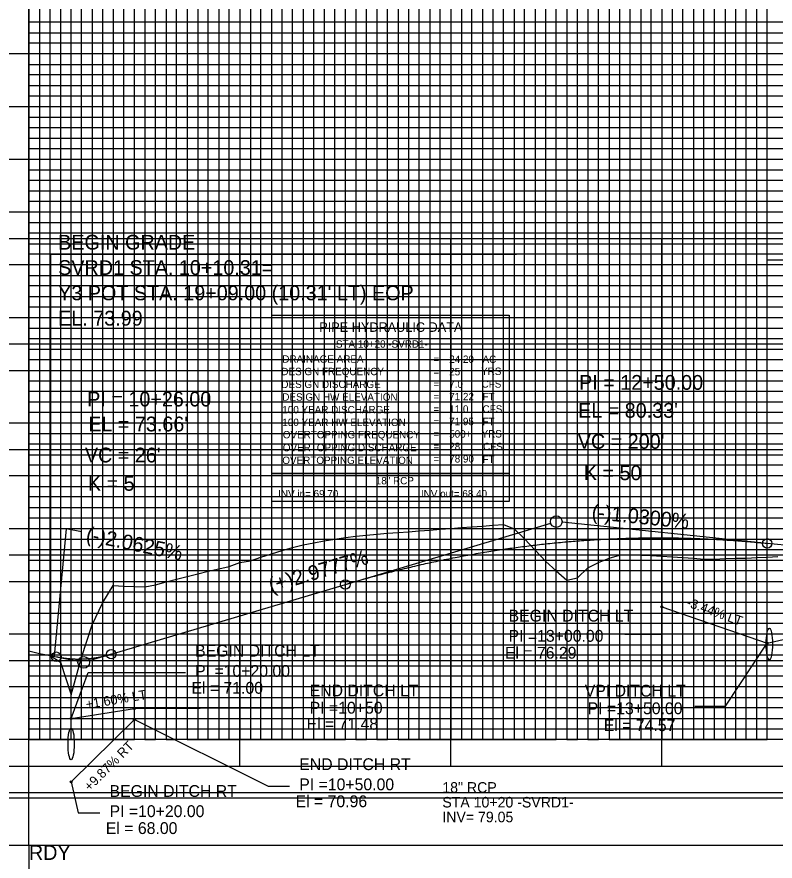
# Model space of a CAD drawing. Extents: x 2345490 to 2436403, y 465165 to 573888.
# Drawn here: x 2381761.1 to 2382120.5, y 510396.8 to 510796.9 of the extents above; entities that cross this region are included whole.
import ezdxf

# ---------------------------------------------------------------- set-up
doc = ezdxf.new("R2010")
doc.units = 0
for name, color, linetype in [('Old_Level_1', 7, 'Continuous'), ('Old_Level_18', 7, 'Continuous'), ('Old_Level_2', 7, 'Continuous'), ('Old_Level_3', 7, 'Continuous'), ('Old_Level_4', 7, 'Continuous'), ('Old_Level_41', 7, 'Continuous'), ('Old_Level_42', 7, 'Continuous'), ('Old_Level_43', 7, 'Continuous'), ('Old_Level_50', 7, 'Continuous'), ('Old_Level_51', 7, 'Continuous'), ('Old_Level_57', 7, 'Continuous'), ('Old_Level_63', 7, 'Continuous'), ('Prop Vertical Profile Grade', 7, 'Continuous')]:
    doc.layers.add(name, color=color, linetype=linetype)

msp = doc.modelspace()

# ---------------------------------------------------------------- linework, layer by layer
at = {"layer": 'Old_Level_1'}
msp.add_lwpolyline([(2381766.799, 510496.38628), (2381771.799, 510495.26652), (2381776.799, 510494.29703), (2381781.799, 510491.09236), (2381786.799, 510475.545), (2381791.799, 510493.23682), (2381796.799, 510508.82896), (2381801.799, 510519.43585), (2381806.799, 510527.46772), (2381811.799, 510527.16316), (2381816.799, 510526.92701), (2381821.799, 510526.73293), (2381826.799, 510527.68325), (2381831.799, 510529.13877), (2381836.799, 510530.47008), (2381841.799, 510531.75771), (2381846.799, 510533.00023), (2381851.799, 510534.19626), (2381856.799, 510535.34447), (2381861.799, 510536.44358), (2381866.799, 510538.26535), (2381871.799, 510539.18964), (2381876.799, 510540.85295), (2381881.799, 510542.44657), (2381886.799, 510543.96872), (2381891.799, 510545.41772), (2381896.799, 510546.68661), (2381901.799, 510547.6733), (2381906.799, 510548.57556), (2381911.799, 510549.39239), (2381916.799, 510550.12286), (2381921.799, 510550.76618), (2381926.799, 510551.32163), (2381931.799, 510551.78859), (2381936.799, 510552.17014), (2381941.799, 510552.5288), (2381946.799, 510552.88746), (2381951.799, 510553.34688), (2381956.799, 510553.71799), (2381961.799, 510554.0891), (2381966.799, 510554.46021), (2381971.799, 510554.83132), (2381976.799, 510555.20243), (2381981.799, 510555.57354), (2381986.799, 510555.94465), (2381991.799, 510556.34881), (2381996.799, 510554.23512), (2382001.799, 510549.54421), (2382006.799, 510544.21219), (2382011.799, 510538.85622), (2382016.799, 510534.42474), (2382021.799, 510529.99327), (2382026.799, 510531.06065), (2382031.799, 510535.83309), (2382036.799, 510538.39836), (2382041.799, 510540.30035), (2382046.799, 510541.74515), (2382051.799, 510541.98873), (2382056.799, 510541.81563), (2382061.799, 510541.64254), (2382066.799, 510541.39711), (2382071.799, 510541.05134), (2382076.799, 510540.72909), (2382081.799, 510540.40571), (2382086.799, 510539.94628), (2382091.799, 510539.9297), (2382096.799, 510540.14654), (2382101.799, 510540.31913), (2382106.799, 510540.43366), (2382111.799, 510540.67643), (2382116.799, 510540.9192), (2382121.799, 510541.16197)], dxfattribs=at)
at = {"layer": 'Old_Level_18'}
msp.add_lwpolyline([(2383216.79875, 511479.3835), (2381716.79875, 511479.3835), (2381716.79875, 510429.3835), (2383216.79875, 510429.3835)], close=True, dxfattribs=at)
at = {"layer": 'Old_Level_2'}
for p, q in [((2381777.109, 510684.44001), (2381997.96282, 510684.47515)), ((2381777.109, 510494.2375), (2381777.109, 510684.44001)), ((2382116.799, 510681.70631), (2382256.61089, 510681.70631)), ((2382116.799, 510547.3835), (2382116.799, 510681.70631)), ((2382116.799, 510547.3835), (2382019.53453, 510557.40174)), ((2381784.50848, 510554.29431), (2381778.8217, 510494.02737)), ((2381791.76888, 510552.84223), (2381784.50848, 510554.29431)), ((2381916.799, 510527.90671), (2382014.16336, 510556.89869)), ((2381779.799, 510493.66475), (2381790.10569, 510491.539)), ((2381805.799, 510494.85448), (2381795.43464, 510491.76831))]:
    msp.add_line(p, q, dxfattribs=at)
for centre, radius in [((2382016.799, 510557.6835), 2.75), ((2382116.799, 510547.3835), 2.25), ((2381916.799, 510527.90671), 2.25), ((2381805.799, 510494.85448), 2.25), ((2381779.799, 510493.66475), 2.25), ((2381792.799, 510490.9835), 2.75)]:
    msp.add_circle(centre, radius, dxfattribs=at)
at = {"layer": 'Old_Level_3'}
for p, q in [((2382066.799, 510504.39502), (2382066.799, 510517.2835)), ((2382066.799, 510517.2835), (2382116.799, 510500.0835)), ((2382116.799, 510500.0835), (2382166.799, 510511.3835)), ((2382049.36634, 510504.39502), (2382066.799, 510504.39502)), ((2382097.05969, 510470.20539), (2382116.799, 510500.0835)), ((2381786.799, 510464.3835), (2381794.9392, 510486.13954)), ((2381794.9392, 510486.13954), (2381841.03359, 510486.13954)), ((2381786.799, 510464.3835), (2381816.799, 510469.1835)), ((2381816.799, 510469.1835), (2381879.16663, 510469.46159)), ((2381879.16663, 510469.46159), (2381892.35737, 510469.46159)), ((2382082.54842, 510470.20539), (2382097.05969, 510470.20539)), ((2381786.799, 510434.3835), (2381816.799, 510463.9835)), ((2381816.799, 510463.9835), (2381880.13742, 510432.37177)), ((2381786.799, 510434.3835), (2381790.19861, 510419.66303)), ((2381880.13742, 510432.37177), (2381890.40218, 510432.37177)), ((2381790.19861, 510419.66303), (2381800.46337, 510419.66303))]:
    msp.add_line(p, q, dxfattribs=at)
for centre in [(2382066.799, 510517.2835), (2382116.799, 510500.0835), (2381816.799, 510469.1835), (2381786.799, 510464.3835), (2381816.799, 510463.9835), (2381786.799, 510434.3835)]:
    msp.add_circle(centre, 0.5, dxfattribs=at)
for centre in [(2382117.799, 510499.6835), (2381786.799, 510452.3835)]:
    msp.add_ellipse(centre, major_axis=(0, 7.5), ratio=0.195724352, dxfattribs=at)
at = {"layer": 'Old_Level_4'}
for p, q in [((2381882.02849, 510655.45163), (2381994.52849, 510655.45163)), ((2381882.02849, 510580.45163), (2381882.02849, 510655.45163)), ((2381994.52849, 510655.45163), (2381994.52849, 510580.45163)), ((2381994.52849, 510580.45163), (2381882.02849, 510580.45163))]:
    msp.add_line(p, q, dxfattribs=at)
msp.add_lwpolyline([(2381882.02849, 510580.45163), (2381994.52849, 510580.45163), (2381994.52849, 510567.23663), (2381882.02849, 510567.23663)], close=True, dxfattribs=at)
at = {"layer": 'Old_Level_41'}
msp.add_line((2383216.79875, 510454.3835), (2381716.79875, 510454.3835), dxfattribs=at)
for points in [[(2381766.79875, 511479.3835), (2381766.79875, 510454.3835), (2381816.79875, 510454.3835), (2381816.79875, 511479.3835)], [(2381791.79875, 510454.3835), (2381791.79875, 511479.3835)], [(2381841.79875, 511479.3835), (2381841.79875, 510454.3835), (2381891.79875, 510454.3835), (2381891.79875, 511479.3835)], [(2381866.79875, 511479.3835), (2381866.79875, 510454.3835), (2381916.79875, 510454.3835), (2381916.79875, 511479.3835)], [(2381941.79875, 511479.3835), (2381941.79875, 510454.3835), (2381991.79875, 510454.3835), (2381991.79875, 511479.3835)], [(2381966.79875, 511479.3835), (2381966.79875, 510454.3835), (2382016.79875, 510454.3835), (2382016.79875, 511479.3835)], [(2382041.79875, 511479.3835), (2382041.79875, 510454.3835), (2382091.79875, 510454.3835), (2382091.79875, 511479.3835)], [(2382066.79875, 511479.3835), (2382066.79875, 510454.3835), (2382116.79875, 510454.3835), (2382116.79875, 511479.3835)], [(2383216.79875, 510779.3835), (2381716.79875, 510779.3835), (2381716.79875, 510729.3835), (2383216.79875, 510729.3835)], [(2383216.79875, 510704.3835), (2381716.79875, 510704.3835), (2381716.79875, 510754.3835), (2383216.79875, 510754.3835)], [(2383216.79875, 510679.3835), (2381716.79875, 510679.3835), (2381716.79875, 510629.3835), (2383216.79875, 510629.3835)], [(2383216.79875, 510579.3835), (2381716.79875, 510579.3835), (2381716.79875, 510529.3835), (2383216.79875, 510529.3835)], [(2383216.79875, 510504.3835), (2381716.79875, 510504.3835), (2381716.79875, 510554.3835), (2383216.79875, 510554.3835)], [(2383216.79875, 510479.3835), (2381716.79875, 510479.3835)]]:
    msp.add_lwpolyline(points, dxfattribs=at)
at = {"layer": 'Old_Level_42'}
msp.add_lwpolyline([(2383216.79875, 510604.3835), (2381716.79875, 510604.3835), (2381716.79875, 510654.3835), (2383216.79875, 510654.3835)], dxfattribs=at)
at = {"layer": 'Old_Level_43'}
for points in [[(2381771.79875, 511479.3835), (2381771.79875, 510454.3835), (2381776.79875, 510454.3835), (2381776.79875, 511479.3835)], [(2381781.79875, 511479.3835), (2381781.79875, 510454.3835), (2381786.79875, 510454.3835), (2381786.79875, 511479.3835)], [(2381796.79875, 511479.3835), (2381796.79875, 510454.3835), (2381801.79875, 510454.3835), (2381801.79875, 511479.3835)], [(2381806.79875, 511479.3835), (2381806.79875, 510454.3835), (2381811.79875, 510454.3835), (2381811.79875, 511479.3835)], [(2381821.79875, 511479.3835), (2381821.79875, 510454.3835), (2381826.79875, 510454.3835), (2381826.79875, 511479.3835)], [(2381831.79875, 511479.3835), (2381831.79875, 510454.3835), (2381836.79875, 510454.3835), (2381836.79875, 511479.3835)], [(2381846.79875, 511479.3835), (2381846.79875, 510454.3835), (2381851.79875, 510454.3835), (2381851.79875, 511479.3835)], [(2381856.79875, 511479.3835), (2381856.79875, 510454.3835), (2381861.79875, 510454.3835), (2381861.79875, 511479.3835)], [(2381871.79875, 511479.3835), (2381871.79875, 510454.3835), (2381876.79875, 510454.3835), (2381876.79875, 511479.3835)], [(2381881.79875, 511479.3835), (2381881.79875, 510454.3835), (2381886.79875, 510454.3835), (2381886.79875, 511479.3835)], [(2381896.79875, 511479.3835), (2381896.79875, 510454.3835), (2381901.79875, 510454.3835), (2381901.79875, 511479.3835)], [(2381906.79875, 511479.3835), (2381906.79875, 510454.3835), (2381911.79875, 510454.3835), (2381911.79875, 511479.3835)], [(2381921.79875, 511479.3835), (2381921.79875, 510454.3835), (2381926.79875, 510454.3835), (2381926.79875, 511479.3835)], [(2381931.79875, 510454.3835), (2381936.79875, 510454.3835), (2381936.79875, 511479.3835)], [(2381931.79875, 511479.3835), (2381931.79875, 510454.3835)], [(2381946.79875, 511479.3835), (2381946.79875, 510454.3835), (2381951.79875, 510454.3835), (2381951.79875, 511479.3835)], [(2381956.79875, 511479.3835), (2381956.79875, 510454.3835), (2381961.79875, 510454.3835), (2381961.79875, 511479.3835)], [(2381971.79875, 511479.3835), (2381971.79875, 510454.3835), (2381976.79875, 510454.3835), (2381976.79875, 511479.3835)], [(2381981.79875, 511479.3835), (2381981.79875, 510454.3835), (2381986.79875, 510454.3835), (2381986.79875, 511479.3835)], [(2381996.79875, 511479.3835), (2381996.79875, 510454.3835), (2382001.79875, 510454.3835), (2382001.79875, 511479.3835)], [(2382006.79875, 511479.3835), (2382006.79875, 510454.3835), (2382011.79875, 510454.3835), (2382011.79875, 511479.3835)], [(2382021.79875, 511479.3835), (2382021.79875, 510454.3835), (2382026.79875, 510454.3835), (2382026.79875, 511479.3835)], [(2382031.79875, 511479.3835), (2382031.79875, 510454.3835), (2382036.79875, 510454.3835), (2382036.79875, 511479.3835)], [(2382046.79875, 511479.3835), (2382046.79875, 510454.3835), (2382051.79875, 510454.3835), (2382051.79875, 511479.3835)], [(2382056.79875, 511479.3835), (2382056.79875, 510454.3835), (2382061.79875, 510454.3835), (2382061.79875, 511479.3835)], [(2382071.79875, 511479.3835), (2382071.79875, 510454.3835), (2382076.79875, 510454.3835), (2382076.79875, 511479.3835)], [(2382081.79875, 511479.3835), (2382081.79875, 510454.3835), (2382086.79875, 510454.3835), (2382086.79875, 511479.3835)], [(2382096.79875, 511479.3835), (2382096.79875, 510454.3835), (2382111.79875, 510454.3835), (2382111.79875, 511479.3835)], [(2382101.79875, 511479.3835), (2382101.79875, 510454.3835), (2382106.79875, 510454.3835), (2382106.79875, 511479.3835)], [(2382101.79875, 511478.7835), (2382101.79875, 510454.3835), (2382106.79875, 510454.3835), (2382106.79875, 511478.7835)], [(2383166.79875, 510794.3835), (2381766.79875, 510794.3835), (2381766.79875, 510789.3835), (2383166.79875, 510789.3835)], [(2383166.79875, 510784.3835), (2381766.79875, 510784.3835), (2381766.79875, 510774.3835), (2383166.79875, 510774.3835)], [(2383166.79875, 510769.3835), (2381766.79875, 510769.3835), (2381766.79875, 510764.3835), (2383166.79875, 510764.3835)], [(2383166.79875, 510759.3835), (2381766.79875, 510759.3835), (2381766.79875, 510749.3835), (2383166.79875, 510749.3835)], [(2383166.79875, 510744.3835), (2381766.79875, 510744.3835), (2381766.79875, 510739.3835), (2383166.79875, 510739.3835)], [(2383166.79875, 510734.3835), (2381766.79875, 510734.3835), (2381766.79875, 510724.3835), (2383166.79875, 510724.3835)], [(2383166.79875, 510719.3835), (2381766.79875, 510719.3835), (2381766.79875, 510714.3835), (2383166.79875, 510714.3835)], [(2383166.79875, 510709.3835), (2381766.79875, 510709.3835), (2381766.79875, 510699.3835), (2383166.79875, 510699.3835)], [(2383166.79875, 510694.3835), (2381766.79875, 510694.3835), (2381766.79875, 510689.3835), (2383166.79875, 510689.3835)], [(2383166.79875, 510684.3835), (2381766.79875, 510684.3835), (2381766.79875, 510674.3835), (2383166.79875, 510674.3835)], [(2383166.79875, 510669.3835), (2381766.79875, 510669.3835), (2381766.79875, 510664.3835), (2383166.79875, 510664.3835)], [(2383166.79875, 510659.3835), (2381766.79875, 510659.3835)], [(2381766.79875, 510649.3835), (2383166.79875, 510649.3835)], [(2383166.79875, 510644.3835), (2381766.79875, 510644.3835), (2381766.79875, 510639.3835), (2383166.79875, 510639.3835)], [(2383166.79875, 510634.3835), (2381766.79875, 510634.3835)], [(2381766.79875, 510624.3835), (2383166.79875, 510624.3835)], [(2383166.79875, 510619.3835), (2381766.79875, 510619.3835), (2381766.79875, 510614.3835), (2383166.79875, 510614.3835)], [(2383166.79875, 510609.3835), (2381766.79875, 510609.3835), (2381766.79875, 510599.3835), (2383166.79875, 510599.3835)], [(2383166.79875, 510594.3835), (2381766.79875, 510594.3835), (2381766.79875, 510589.3835), (2383166.79875, 510589.3835)], [(2383166.79875, 510584.3835), (2381766.79875, 510584.3835), (2381766.79875, 510574.3835), (2383166.79875, 510574.3835)], [(2383166.79875, 510569.3835), (2381766.79875, 510569.3835), (2381766.79875, 510564.3835), (2383166.79875, 510564.3835)], [(2383166.79875, 510559.3835), (2381766.79875, 510559.3835), (2381766.79875, 510549.3835), (2383166.79875, 510549.3835)], [(2383166.79875, 510544.3835), (2381766.79875, 510544.3835), (2381766.79875, 510539.3835), (2383166.79875, 510539.3835)], [(2383166.79875, 510534.3835), (2381766.79875, 510534.3835), (2381766.79875, 510524.3835), (2383166.79875, 510524.3835)], [(2383166.79875, 510519.3835), (2381766.79875, 510519.3835), (2381766.79875, 510514.3835), (2383166.79875, 510514.3835)], [(2383166.79875, 510509.3835), (2381766.79875, 510509.3835), (2381766.79875, 510499.3835), (2383166.79875, 510499.3835)], [(2383166.79875, 510494.3835), (2381766.79875, 510494.3835), (2381766.79875, 510489.3835), (2383166.79875, 510489.3835)], [(2383166.79875, 510484.3835), (2381766.79875, 510484.3835), (2381766.79875, 510474.3835), (2383166.79875, 510474.3835)], [(2383166.79875, 510469.3835), (2381766.79875, 510469.3835), (2381766.79875, 510464.3835), (2383166.79875, 510464.3835)], [(2383166.79875, 510459.3835), (2381766.79875, 510459.3835)]]:
    msp.add_lwpolyline(points, dxfattribs=at)
at = {"layer": 'Old_Level_50'}
msp.add_lwpolyline([(2383229.29875, 511481.9335), (2381562.79875, 511481.9335), (2381562.79875, 510426.8335), (2383229.29875, 510426.8335)], close=True, dxfattribs=at)
at = {"layer": 'Old_Level_51'}
msp.add_lwpolyline([(2383233.79875, 511504.3835), (2381549.79875, 511504.3835), (2381549.79875, 510404.3835), (2383233.79875, 510404.3835)], close=True, dxfattribs=at)
at = {"layer": 'Old_Level_57'}
for p, q in [((2381716.79925, 510691.88375), (2383066.79875, 510691.88375)), ((2381766.79875, 510441.88375), (2381766.79875, 510691.88375)), ((2381866.79875, 510441.88375), (2381866.79875, 510691.88375)), ((2381966.79875, 510441.88375), (2381966.79875, 510691.88375)), ((2382066.79875, 510441.88375), (2382066.79875, 510691.88375)), ((2381716.79925, 510641.88375), (2383066.79875, 510641.88375)), ((2381716.79925, 510591.88375), (2383066.79875, 510591.88375)), ((2381716.79925, 510541.88375), (2383066.79875, 510541.88375)), ((2381716.799, 510491.88375), (2383066.79875, 510491.88375)), ((2381716.79925, 510441.88375), (2383066.79875, 510441.88375))]:
    msp.add_line(p, q, dxfattribs=at)
at = {"layer": 'Old_Level_63'}
for q in [(2381766.799, 512904.3835), (2382366.799, 510404.3835), (2381766.799, 507904.3835)]:
    msp.add_line((2381766.799, 510404.3835), q, dxfattribs=at)
at = {"layer": 'Prop Vertical Profile Grade'}
for p, q in [((2382166.799, 510542.02672), (2382116.799, 510547.3835)), ((2381805.799, 510494.85448), (2381916.799, 510527.90671)), ((2381776.799, 510494.2835), (2381779.799, 510493.66475))]:
    msp.add_line(p, q, dxfattribs=at)
for points in [[(2381916.799, 510527.90671), (2381920.799, 510529.08175), (2381924.799, 510530.22473), (2381928.799, 510531.33565), (2381932.799, 510532.41451), (2381936.799, 510533.4613), (2381940.799, 510534.47604), (2381944.799, 510535.45871), (2381948.799, 510536.40932), (2381952.799, 510537.32787), (2381956.799, 510538.21436), (2381960.799, 510539.06878), (2381964.799, 510539.89115), (2381968.799, 510540.68145), (2381972.799, 510541.43969), (2381976.799, 510542.16588), (2381980.799, 510542.85999), (2381984.799, 510543.52205), (2381988.799, 510544.15205), (2381992.799, 510544.74998), (2381996.799, 510545.31586), (2382000.799, 510545.84967), (2382004.799, 510546.35142), (2382008.799, 510546.82111), (2382012.799, 510547.25874), (2382016.799, 510547.6643), (2382020.799, 510548.03781), (2382024.799, 510548.37925), (2382028.799, 510548.68863), (2382032.799, 510548.96596), (2382036.799, 510549.21121), (2382040.799, 510549.42441), (2382044.799, 510549.60555), (2382048.799, 510549.75462), (2382052.799, 510549.87164), (2382056.799, 510549.95659), (2382060.799, 510550.00948), (2382064.799, 510550.03031), (2382068.799, 510550.01908), (2382072.799, 510549.97578), (2382076.799, 510549.90043), (2382080.799, 510549.79301), (2382084.799, 510549.65353), (2382088.799, 510549.482), (2382092.799, 510549.27839), (2382096.799, 510549.04273), (2382100.799, 510548.77501), (2382104.799, 510548.47522), (2382108.799, 510548.14338), (2382112.799, 510547.77947), (2382116.799, 510547.3835)], [(2381779.799, 510493.66475), (2381780.319, 510493.56012), (2381780.839, 510493.46073), (2381781.359, 510493.36659), (2381781.879, 510493.27768), (2381782.399, 510493.19402), (2381782.919, 510493.1156), (2381783.439, 510493.04242), (2381783.959, 510492.97449), (2381784.479, 510492.91179), (2381784.999, 510492.85434), (2381785.519, 510492.80213), (2381786.039, 510492.75516), (2381786.559, 510492.71343), (2381787.079, 510492.67695), (2381787.599, 510492.6457), (2381788.119, 510492.6197), (2381788.639, 510492.59894), (2381789.159, 510492.58342), (2381789.679, 510492.57314), (2381790.199, 510492.56811), (2381790.719, 510492.56831), (2381791.239, 510492.57376), (2381791.759, 510492.58445), (2381792.279, 510492.60038), (2381792.799, 510492.62156), (2381793.319, 510492.64797), (2381793.839, 510492.67963), (2381794.359, 510492.71653), (2381794.879, 510492.75867), (2381795.399, 510492.80605), (2381795.919, 510492.85868), (2381796.439, 510492.91654), (2381796.959, 510492.97965), (2381797.479, 510493.048), (2381797.999, 510493.12159), (2381798.519, 510493.20043), (2381799.039, 510493.2845), (2381799.559, 510493.37382), (2381800.079, 510493.46838), (2381800.599, 510493.56818), (2381801.119, 510493.67322), (2381801.639, 510493.7835), (2381802.159, 510493.89903), (2381802.679, 510494.0198), (2381803.199, 510494.14581), (2381803.719, 510494.27706), (2381804.239, 510494.41355), (2381804.759, 510494.55529), (2381805.279, 510494.70226), (2381805.799, 510494.85448)]]:
    msp.add_spline(points, degree=3, dxfattribs=at)

# ---------------------------------------------------------------- texts
at = {"layer": 'Old_Level_2'}
for s, height, p in [('BEGIN GRADE', 7.0000005, (2381780.66053, 510686.59204)), ('SVRD1 STA. 10+10.31=', 7.0000005, (2381780.66053, 510674.59203)), ("Y3 POT STA. 19+09.00 (10.31' LT) EOP", 7.0000005, (2381780.66053, 510662.59203)), ('EL. 73.99', 7.000001, (2381780.66053, 510650.59203)), ('PI = 12+50.00', 7, (2382027.60025, 510620.1666)), ('PI = 10+26.00', 7, (2381794.42908, 510612.27802)), ("EL = 80.33'", 7, (2382027.11891, 510606.90534)), ("EL = 73.66'", 7, (2381794.91042, 510600.46076)), ("VC = 200'", 7, (2382026.98125, 510592.22043)), ("VC = 26'", 7, (2381793.32874, 510585.75548)), ('K = 50', 7, (2382029.86927, 510577.34015)), ('K = 5', 7, (2381794.77276, 510572.31922))]:
    msp.add_text(s, height=height, dxfattribs=at).set_placement(p)
for s, rotation, p in [('(-)1.0300%', 354.1192724, (2382033.32422, 510558.99727)), ('(-)2.0625%', 348.3461594, (2381793.46367, 510548.57707)), ('(+)2.9777%', 16.5818398, (2381881.68354, 510523.93216))]:
    msp.add_text(s, height=7, rotation=rotation, dxfattribs=at).set_placement(p)
at = {"layer": 'Old_Level_3'}
for s, height, rotation, p in [('-3.44% LT', 4.48, 340.1418463, (2382078.11388, 510517.66527)), ('BEGIN DITCH LT', 5.6000004, 360, (2381994.18539, 510510.32954)), ('PI =13+00.00', 5.6000004, 360, (2381994.18539, 510500.76575)), ('BEGIN DITCH LT', 5.6000004, 360, (2381845.59083, 510493.71041)), ('El = 76.29', 5.6, 360, (2381992.42877, 510492.74647)), ('PI =10+20.00', 5.6000004, 360, (2381845.59083, 510484.14662)), ('El = 71.00', 5.6, 360, (2381843.83422, 510476.12734)), ('+1.60% LT', 4.48, 9.4623222, (2381794.14851, 510468.85455)), ('END DITCH LT', 5.6000004, 360, (2381899.88883, 510474.88935)), ('VPI DITCH LT', 5.6000004, 360, (2382030.29962, 510474.76123)), ('PI =10+50', 5.6, 360, (2381899.88883, 510466.69466)), ('PI =13+50.00', 5.6000004, 360, (2382031.66968, 510466.42017)), ('El = 71.48', 5.6, 360, (2381898.42499, 510459.06574)), ('El = 74.57', 5.6, 360, (2382039.30832, 510458.39708)), ('+9.87% RT', 4.48, 44.9999778, (2381795.62558, 510429.66969)), ('END DITCH RT', 5.6000004, 360, (2381894.95942, 510439.94264)), ('PI =10+50.00', 5.6000004, 360, (2381894.95942, 510430.37886)), ('BEGIN DITCH RT', 5.6000004, 360, (2381805.02061, 510427.2339)), ('El = 70.96', 5.6, 360, (2381893.2028, 510422.35957)), ('PI =10+20.00', 5.6000004, 360, (2381805.02061, 510417.67011)), ('El = 68.00', 5.6, 360, (2381803.26399, 510409.65083))]:
    msp.add_text(s, height=height, rotation=rotation, dxfattribs=at).set_placement(p)
for s, height, p in [('18" RCP', 4.999999, (2381962.7762, 510429.22611)), ('STA 10+20 -SVRD1-', 4.9999995, (2381962.7762, 510422.22611)), ('INV= 79.05', 4.999999, (2381962.7762, 510415.22611))]:
    msp.add_text(s, height=height, dxfattribs=at).set_placement(p)
at = {"layer": 'Old_Level_4'}
for s, height, p in [('PIPE HYDRAULIC DATA', 4.49985, (2381904.42849, 510647.62663)), ('STA 10+20 -SVRD1-', 3.4998, (2381912.32224, 510640.12638)), ('DRAINAGE AREA', 3.49995, (2381886.92849, 510633.00163)), ('=        ', 3.49995, (2381958.57849, 510632.90163)), ('24.20', 3.49995, (2381966.03899, 510632.90118)), ('AC', 3.49995, (2381981.85349, 510632.90163)), ('DESIGN FREQUENCY', 3.49995, (2381886.47849, 510627.07663)), ('=        ', 3.49995, (2381958.57849, 510627.00163)), ('25', 3.49995, (2381966.03899, 510627.00123)), ('YRS', 3.49995, (2381981.15349, 510627.20163)), ('DESIGN DISCHARGE', 3.49995, (2381886.47849, 510621.00163)), ('=        ', 3.49995, (2381958.57849, 510621.10163)), ('7.0', 3.49995, (2381966.03899, 510621.10128)), ('CFS', 3.49995, (2381981.37849, 510621.17663)), ('DESIGN HW ELEVATION', 3.49995, (2381886.92849, 510615.00163)), ('=        ', 3.49995, (2381958.57849, 510615.20163)), ('71.22', 3.49995, (2381966.03899, 510615.20133)), ('FT', 3.49995, (2381981.85349, 510615.20163)), ('100 YEAR DISCHARGE', 3.49995, (2381886.92849, 510609.00163)), ('=        ', 3.49995, (2381958.57849, 510609.30163)), ('11.0', 3.49995, (2381966.03899, 510609.30138)), ('CFS', 3.49995, (2381981.85349, 510609.30163)), ('100 YEAR HW ELEVATION', 3.49995, (2381886.92849, 510603.00163)), ('=        ', 3.49995, (2381958.57849, 510603.40163)), ('71.95', 3.49995, (2381966.03899, 510603.40143)), ('FT', 3.49995, (2381981.85349, 510603.40163)), ('500+', 3.49995, (2381966.03899, 510597.50148)), ('YRS', 3.49995, (2381981.37849, 510597.55163)), ('OVERTOPPING FREQUENCY', 3.49995, (2381887.15349, 510597.15163)), ('=        ', 3.49995, (2381958.57849, 510597.50163)), ('OVERTOPPING DISCHARGE', 3.49995, (2381887.15349, 510591.02663)), ('=        ', 3.49995, (2381958.57849, 510591.60163)), ('28', 3.49995, (2381966.03899, 510591.60153)), ('CFS', 3.49995, (2381982.07849, 510591.52663)), ('78.90', 3.49995, (2381966.03899, 510585.70158)), ('FT', 3.49995, (2381981.85349, 510585.50163)), ('OVERTOPPING ELEVATION', 3.49995, (2381886.92849, 510585.00163)), ('=        ', 3.49995, (2381958.57849, 510585.70163)), ('18" RCP', 3.4998, (2381931.23424, 510575.34938)), ('INV in= 69.70', 3.4998, (2381884.96099, 510569.16363)), ('INV out= 68.40', 3.4998, (2381952.63774, 510569.16363))]:
    msp.add_text(s, height=height, dxfattribs=at).set_placement(p)
at = {"layer": 'Old_Level_63'}
msp.add_text('RDY', height=7.000001, dxfattribs=at).set_placement((2381766.799, 510397.3835))

doc.saveas('drawing.dxf')
